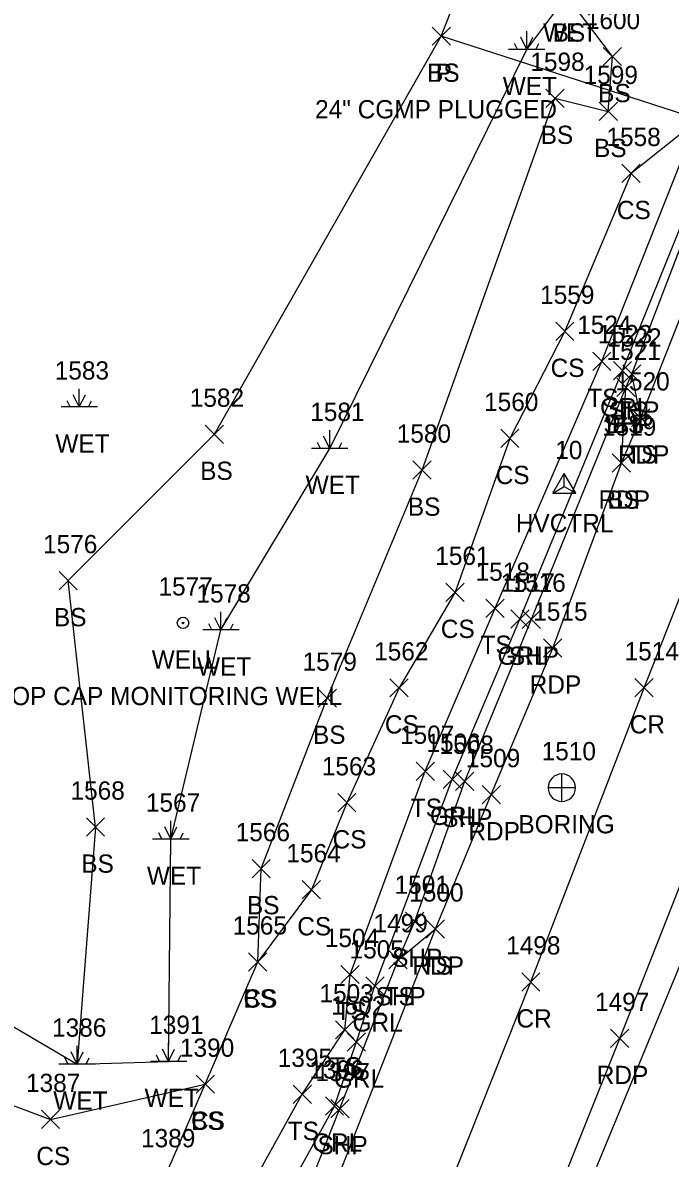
# Model space of a CAD drawing. Extents: x 1554917 to 1555870, y 813367 to 816333.
# Drawn here: x 1555138.3 to 1555209.2, y 813931.9 to 814056.2 of the extents above; entities that cross this region are included whole.
import ezdxf

# ---------------------------------------------------------------- set-up
doc = ezdxf.new("R2010")
doc.units = 0
for name, color, linetype in [('C_A', 7, 'Continuous'), ('C_I', 7, 'Continuous'), ('CPSM', 7, 'Continuous'), ('D_A', 7, 'Continuous'), ('D_C', 7, 'Continuous'), ('D_TIC', 7, 'Continuous'), ('DCP', 7, 'Continuous'), ('G_A', 7, 'Continuous'), ('G_I', 7, 'Continuous'), ('GA_P', 7, 'Continuous'), ('L_A', 7, 'Continuous'), ('L_I', 7, 'Continuous'), ('L_TIC', 7, 'Continuous'), ('LELB', 7, 'Continuous'), ('LWET', 7, 'Continuous'), ('P_A', 7, 'Continuous'), ('P_I', 7, 'Continuous'), ('P_TIC', 7, 'Continuous'), ('PET', 7, 'Continuous'), ('PRC', 7, 'Continuous'), ('PSP', 7, 'Continuous'), ('R_A', 7, 'Continuous'), ('R_I', 7, 'Continuous'), ('R_TIC', 7, 'Continuous'), ('RGR', 7, 'Continuous'), ('U_A', 7, 'Continuous'), ('U_C', 7, 'Continuous'), ('U_I', 7, 'Continuous'), ('UWW', 7, 'Continuous')]:
    doc.layers.add(name, color=color, linetype=linetype)

msp = doc.modelspace()

# ---------------------------------------------------------------- linework, layer by layer
at = {"layer": 'CPSM'}
for p, q in [((1555196.38, 814004.7), (1555197.63, 814006.87)), ((1555198.88, 814004.7), (1555197.63, 814006.87)), ((1555197.63, 814005.43), (1555197.63, 814006.87)), ((1555196.38, 814004.7), (1555197.63, 814005.43)), ((1555196.38, 814004.7), (1555198.88, 814004.7)), ((1555197.63, 814005.43), (1555197.63, 814005.43)), ((1555197.63, 814005.43), (1555198.88, 814004.7))]:
    msp.add_line(p, q, dxfattribs=at)
at = {"layer": 'D_TIC'}
for points in [[(1555183.15, 814053.74), (1555185.15, 814055.74)], [(1555185.15, 814053.74), (1555183.15, 814055.74)]]:
    msp.add_lwpolyline(points, dxfattribs=at)
at = {"layer": 'DCP'}
msp.add_lwpolyline([(1555254.85, 814031.94), (1555184.15, 814054.74)], dxfattribs=at)
at = {"layer": 'GA_P'}
for p, q in [((1555197.37, 813972.46), (1555197.37, 813973.96)), ((1555197.37, 813972.46), (1555195.87, 813972.46)), ((1555198.87, 813972.46), (1555197.37, 813972.46)), ((1555197.37, 813970.96), (1555197.37, 813972.46))]:
    msp.add_line(p, q, dxfattribs=at)
for start, end in [(90, 180), (0, 90), (180, 270), (270, 0)]:
    msp.add_arc((1555197.37, 813972.46), 1.5, start, end, dxfattribs=at)
at = {"layer": 'L_TIC'}
for points in [[(1555183.15, 814053.74), (1555185.15, 814055.74)], [(1555185.15, 814053.74), (1555183.15, 814055.74)], [(1555201.9, 814051.51), (1555203.9, 814053.51)], [(1555203.9, 814051.51), (1555201.9, 814053.51)], [(1555195.6, 814046.94), (1555197.6, 814048.94)], [(1555197.6, 814046.94), (1555195.6, 814048.94)], [(1555201.45, 814045.5), (1555203.45, 814047.5)], [(1555203.45, 814045.5), (1555201.45, 814047.5)], [(1555203.95, 814038.71), (1555205.95, 814040.71)], [(1555205.95, 814038.71), (1555203.95, 814040.71)], [(1555196.69, 814021.43), (1555198.69, 814023.43)], [(1555198.69, 814021.43), (1555196.69, 814023.43)], [(1555200.74, 814018.14), (1555202.74, 814020.14)], [(1555202.74, 814018.14), (1555200.74, 814020.14)], [(1555204.03, 814016.75), (1555206.03, 814018.75)], [(1555206.03, 814016.75), (1555204.03, 814018.75)], [(1555203.38, 814015.29), (1555205.38, 814017.29)], [(1555205.38, 814015.29), (1555203.38, 814017.29)], [(1555205.01, 814011.95), (1555207.01, 814013.95)], [(1555207.01, 814011.95), (1555205.01, 814013.95)], [(1555158.28, 814010.16), (1555160.28, 814012.16)], [(1555160.28, 814010.16), (1555158.28, 814012.16)], [(1555190.66, 814009.7), (1555192.66, 814011.7)], [(1555192.66, 814009.7), (1555190.66, 814011.7)], [(1555181.05, 814006.23), (1555183.05, 814008.23)], [(1555183.05, 814006.23), (1555181.05, 814008.23)], [(1555202.89, 814007), (1555204.89, 814009)], [(1555204.89, 814007), (1555202.89, 814009)], [(1555142.26, 813994.13), (1555144.26, 813996.13)], [(1555144.26, 813994.13), (1555142.26, 813996.13)], [(1555184.66, 813992.85), (1555186.66, 813994.85)], [(1555186.66, 813992.85), (1555184.66, 813994.85)], [(1555189.04, 813991.11), (1555191.04, 813993.11)], [(1555191.04, 813991.11), (1555189.04, 813993.11)], [(1555178.53, 813982.39), (1555180.53, 813984.39)], [(1555180.53, 813982.39), (1555178.53, 813984.39)], [(1555170.65, 813981.26), (1555172.65, 813983.26)], [(1555172.65, 813981.26), (1555170.65, 813983.26)], [(1555181.4, 813973.26), (1555183.4, 813975.26)], [(1555183.4, 813973.26), (1555181.4, 813975.26)], [(1555172.8, 813969.81), (1555174.8, 813971.81)], [(1555174.8, 813969.81), (1555172.8, 813971.81)], [(1555145.26, 813967.15), (1555147.26, 813969.15)], [(1555147.26, 813967.15), (1555145.26, 813969.15)], [(1555163.41, 813962.6), (1555165.41, 813964.6)], [(1555165.41, 813962.6), (1555163.41, 813964.6)], [(1555168.92, 813960.29), (1555170.92, 813962.29)], [(1555170.92, 813960.29), (1555168.92, 813962.29)], [(1555182.5, 813955.99), (1555184.5, 813957.99)], [(1555184.5, 813955.99), (1555182.5, 813957.99)], [(1555163.03, 813952.38), (1555165.03, 813954.38)], [(1555165.03, 813952.38), (1555163.03, 813954.38)], [(1555163.03, 813952.38), (1555165.03, 813954.38)], [(1555165.03, 813952.38), (1555163.03, 813954.38)], [(1555178.42, 813952.63), (1555180.42, 813954.63)], [(1555180.42, 813952.63), (1555178.42, 813954.63)], [(1555173.16, 813951.01), (1555175.16, 813953.01)], [(1555175.16, 813951.01), (1555173.16, 813953.01)], [(1555172.57, 813944.95), (1555174.57, 813946.95)], [(1555174.57, 813944.95), (1555172.57, 813946.95)], [(1555157.29, 813939), (1555159.29, 813941)], [(1555159.29, 813939), (1555157.29, 813941)], [(1555157.29, 813939), (1555159.29, 813941)], [(1555159.29, 813939), (1555157.29, 813941)], [(1555167.92, 813937.89), (1555169.92, 813939.89)], [(1555169.92, 813937.89), (1555167.92, 813939.89)], [(1555140.33, 813935.14), (1555142.33, 813937.14)], [(1555142.33, 813935.14), (1555140.33, 813937.14)]]:
    msp.add_lwpolyline(points, dxfattribs=at)
at = {"layer": 'LELB'}
for points in [[(1555161.57, 813925.65), (1555168.92, 813938.89), (1555173.57, 813945.95), (1555174.16, 813952.01), (1555182.4, 813974.26), (1555190.04, 813992.11), (1555201.74, 814019.14), (1555212.19, 814045.46), (1555215.96, 814054.45), (1555221.93, 814072.78), (1555233.01, 814105.58), (1555244.12, 814126.91), (1555239.17, 814141.42), (1555241.48, 814149.75), (1555239.8, 814159.84), (1555236.73, 814168.01), (1555231.65, 814185.57), (1555238.6, 814201.71), (1555239.91, 814224.12), (1555242.5, 814231.73), (1555248.59, 814255.34), (1555259.33, 814293.88), (1555265.42, 814329.58), (1555267.14, 814335.72)], [(1555153.95, 813930.09), (1555158.29, 813940), (1555164.03, 813953.38), (1555164.41, 813963.6), (1555171.65, 813982.26), (1555182.05, 814007.23), (1555196.6, 814047.94), (1555202.45, 814046.5), (1555202.9, 814052.51), (1555197.92, 814059.14), (1555209.24, 814082.57), (1555225.19, 814108.48), (1555231.76, 814126.55), (1555232.99, 814141.48), (1555234.22, 814150.46), (1555236.77, 814156.09), (1555225.98, 814163.26)], [(1555146.26, 813968.15), (1555143.26, 813995.13), (1555159.28, 814011.16), (1555184.15, 814054.74), (1555197, 814087.34), (1555204.67, 814115.04), (1555215.8, 814144.46), (1555222.11, 814148.5), (1555231.58, 814148.96), (1555234.22, 814150.46)], [(1555212.19, 814045.46), (1555204.95, 814039.71), (1555197.69, 814022.43), (1555191.66, 814010.7), (1555185.66, 813993.85), (1555179.53, 813983.39), (1555173.8, 813970.81), (1555169.92, 813961.29), (1555164.03, 813953.38)], [(1555206.01, 814012.95), (1555205.03, 814017.75)], [(1555203.89, 814008), (1555204.38, 814016.29)], [(1555146.26, 813968.15), (1555144.25, 813942.2)], [(1555111.92, 813965.76), (1555119.76, 813951.5), (1555131.06, 813939.98), (1555141.33, 813936.14), (1555158.29, 813940)], [(1555179.42, 813953.63), (1555183.5, 813956.99)]]:
    msp.add_lwpolyline(points, dxfattribs=at)
at = {"layer": 'LWET'}
for p, q in [((1555193.51, 814053.28), (1555192.85, 814054.62)), ((1555193.51, 814053.28), (1555193.51, 814055.28)), ((1555193.51, 814053.28), (1555194.18, 814054.62)), ((1555195.51, 814053.28), (1555191.51, 814053.28)), ((1555192.51, 814053.28), (1555192.18, 814053.95)), ((1555194.51, 814053.28), (1555194.85, 814053.95)), ((1555144.48, 814014.14), (1555144.48, 814016.14)), ((1555143.48, 814014.14), (1555143.15, 814014.81)), ((1555144.48, 814014.14), (1555143.81, 814015.48)), ((1555144.48, 814014.14), (1555145.15, 814015.48)), ((1555145.48, 814014.14), (1555145.81, 814014.81)), ((1555146.48, 814014.14), (1555142.48, 814014.14)), ((1555171.92, 814009.61), (1555171.25, 814010.94)), ((1555171.92, 814009.61), (1555171.92, 814011.61)), ((1555171.92, 814009.61), (1555172.58, 814010.94)), ((1555173.92, 814009.61), (1555169.92, 814009.61)), ((1555170.92, 814009.61), (1555170.58, 814010.27)), ((1555172.92, 814009.61), (1555173.25, 814010.27)), ((1555160.01, 813989.73), (1555159.34, 813991.07)), ((1555160.01, 813989.73), (1555160.01, 813991.73)), ((1555160.01, 813989.73), (1555160.68, 813991.07)), ((1555162.01, 813989.73), (1555158.01, 813989.73)), ((1555159.01, 813989.73), (1555158.68, 813990.4)), ((1555161.01, 813989.73), (1555161.34, 813990.4)), ((1555154.52, 813966.83), (1555154.52, 813968.83)), ((1555153.52, 813966.83), (1555153.18, 813967.5)), ((1555154.52, 813966.83), (1555153.85, 813968.17)), ((1555154.52, 813966.83), (1555155.18, 813968.17)), ((1555155.52, 813966.83), (1555155.85, 813967.5)), ((1555156.52, 813966.83), (1555152.52, 813966.83)), ((1555144.25, 813942.2), (1555144.25, 813944.2)), ((1555154.27, 813942.5), (1555153.6, 813943.83)), ((1555154.27, 813942.5), (1555154.27, 813944.5)), ((1555154.27, 813942.5), (1555154.93, 813943.83)), ((1555143.25, 813942.2), (1555142.91, 813942.87)), ((1555144.25, 813942.2), (1555143.58, 813943.53)), ((1555144.25, 813942.2), (1555144.91, 813943.53)), ((1555145.25, 813942.2), (1555145.58, 813942.87)), ((1555156.27, 813942.5), (1555152.27, 813942.5)), ((1555153.27, 813942.5), (1555152.93, 813943.16)), ((1555155.27, 813942.5), (1555155.6, 813943.16)), ((1555146.25, 813942.2), (1555142.25, 813942.2))]:
    msp.add_line(p, q, dxfattribs=at)
msp.add_lwpolyline([(1555079.52, 813972.15), (1555098.48, 813965.44), (1555111.92, 813965.76), (1555124.09, 813958.62), (1555134.73, 813947.78), (1555144.25, 813942.2), (1555154.27, 813942.5), (1555154.52, 813966.83), (1555160.01, 813989.73), (1555171.92, 814009.61), (1555193.51, 814053.28), (1555197.92, 814059.14), (1555201.96, 814084.83), (1555215.92, 814112.52), (1555222.38, 814128.7), (1555225.01, 814142.8)], dxfattribs=at)
at = {"layer": 'P_TIC'}
for points in [[(1555204.03, 814016.75), (1555206.03, 814018.75)], [(1555206.03, 814016.75), (1555204.03, 814018.75)], [(1555203.38, 814015.29), (1555205.38, 814017.29)], [(1555205.38, 814015.29), (1555203.38, 814017.29)], [(1555205.01, 814011.95), (1555207.01, 814013.95)], [(1555207.01, 814011.95), (1555205.01, 814013.95)], [(1555202.89, 814007), (1555204.89, 814009)], [(1555204.89, 814007), (1555202.89, 814009)], [(1555193.02, 813989.9), (1555195.02, 813991.9)], [(1555195.02, 813989.9), (1555193.02, 813991.9)], [(1555195.36, 813986.75), (1555197.36, 813988.75)], [(1555197.36, 813986.75), (1555195.36, 813988.75)], [(1555205.37, 813982.4), (1555207.37, 813984.4)], [(1555207.37, 813982.4), (1555205.37, 813984.4)], [(1555185.72, 813972.16), (1555187.72, 813974.16)], [(1555187.72, 813972.16), (1555185.72, 813974.16)], [(1555188.63, 813970.7), (1555190.63, 813972.7)], [(1555190.63, 813970.7), (1555188.63, 813972.7)], [(1555180.24, 813956.84), (1555182.24, 813958.84)], [(1555182.24, 813956.84), (1555180.24, 813958.84)], [(1555182.5, 813955.99), (1555184.5, 813957.99)], [(1555184.5, 813955.99), (1555182.5, 813957.99)], [(1555178.42, 813952.63), (1555180.42, 813954.63)], [(1555180.42, 813952.63), (1555178.42, 813954.63)], [(1555192.96, 813950.2), (1555194.96, 813952.2)], [(1555194.96, 813950.2), (1555192.96, 813952.2)], [(1555202.7, 813944.01), (1555204.7, 813946.01)], [(1555204.7, 813944.01), (1555202.7, 813946.01)], [(1555172.05, 813936.33), (1555174.05, 813938.33)], [(1555174.05, 813936.33), (1555172.05, 813938.33)]]:
    msp.add_lwpolyline(points, dxfattribs=at)
at = {"layer": 'PET'}
for points in [[(1555161.36, 813900.53), (1555183.5, 813956.99), (1555189.63, 813971.7), (1555196.36, 813987.75), (1555203.89, 814008), (1555206.01, 814012.95), (1555218.07, 814043.52), (1555227.32, 814068.19), (1555240.79, 814103.21), (1555254.41, 814137.22), (1555273.72, 814186.43), (1555286.72, 814219.57), (1555303.34, 814262.32), (1555319.11, 814302.56), (1555330.34, 814331.97)], [(1555182.57, 813892.25), (1555203.7, 813945.01), (1555216.85, 813978.34), (1555228.72, 814008.85), (1555239.47, 814035.47), (1555248.64, 814059.88), (1555262.92, 814096.01), (1555276.68, 814131.3), (1555286.36, 814156.33), (1555297.11, 814184.04), (1555306.67, 814209.51), (1555324.28, 814253.26), (1555340.35, 814293.54), (1555352.6, 814325.05)]]:
    msp.add_lwpolyline(points, dxfattribs=at)
at = {"layer": 'PRC'}
msp.add_lwpolyline([(1554976.76, 813382.18), (1554992.84, 813427.9), (1555014.07, 813486.01), (1555030.62, 813532.31), (1555046.37, 813573.08), (1555064.69, 813621.19), (1555082.41, 813667.53), (1555112.1, 813744.1), (1555110.69, 813739.79), (1555136.16, 813805.74), (1555152.52, 813846.93), (1555172.03, 813896.18), (1555193.96, 813951.2), (1555206.37, 813983.4), (1555218.13, 814013.22), (1555228.65, 814039.26), (1555237.93, 814064.31), (1555252.22, 814099.76), (1555265.8, 814135.89), (1555275.26, 814160.09), (1555297.17, 814214.77), (1555313.83, 814257.94), (1555329.72, 814298.26), (1555342.03, 814329.92)], dxfattribs=at)
at = {"layer": 'PSP'}
for points in [[(1555160.79, 813906.47), (1555173.05, 813937.33), (1555179.42, 813953.63), (1555181.24, 813957.84), (1555186.72, 813973.16), (1555194.02, 813990.9), (1555204.38, 814016.29), (1555205.03, 814017.75), (1555215.29, 814044.5), (1555224.66, 814068.93), (1555238.68, 814103.48), (1555248.96, 814130.73), (1555261.62, 814162.67), (1555270.99, 814187.05), (1555283.98, 814220.8), (1555300.65, 814263.34), (1555316.51, 814303.51), (1555327.36, 814331.38)], [(1555197.67, 813922.42), (1555211.91, 813956.86), (1555220.23, 813977.15), (1555231.8, 814008.2), (1555242.48, 814034.48), (1555251.86, 814058.97), (1555266.04, 814094.8), (1555272.79, 814112.73), (1555286.23, 814147.2), (1555300.19, 814183.09), (1555310.34, 814208.22), (1555327.38, 814252.3), (1555343.49, 814292.44), (1555355.29, 814323.57)]]:
    msp.add_lwpolyline(points, dxfattribs=at)
at = {"layer": 'R_TIC'}
for points in [[(1555203.01, 814017.12), (1555205.01, 814019.12)], [(1555205.01, 814017.12), (1555203.01, 814019.12)], [(1555191.77, 813989.92), (1555193.77, 813991.92)], [(1555193.77, 813989.92), (1555191.77, 813991.92)], [(1555184.36, 813972.38), (1555186.36, 813974.38)], [(1555186.36, 813972.38), (1555184.36, 813974.38)], [(1555175.88, 813949.76), (1555177.88, 813951.76)], [(1555177.88, 813949.76), (1555175.88, 813951.76)], [(1555173.85, 813943.62), (1555175.85, 813945.62)], [(1555175.85, 813943.62), (1555173.85, 813945.62)], [(1555171.45, 813936.61), (1555173.45, 813938.61)], [(1555173.45, 813936.61), (1555171.45, 813938.61)]]:
    msp.add_lwpolyline(points, dxfattribs=at)
at = {"layer": 'RGR'}
msp.add_lwpolyline([(1555159.27, 813917.51), (1555164.57, 813923.33), (1555172.45, 813937.61), (1555174.85, 813944.62), (1555176.88, 813950.76), (1555185.36, 813973.38), (1555192.77, 813990.92), (1555204.01, 814018.12), (1555214.74, 814044.68), (1555224.38, 814069.2), (1555237.86, 814103.71), (1555245.14, 814124.79), (1555246.27, 814138.04)], dxfattribs=at)
at = {"layer": 'UWW'}
for radius in [0.625, 0.0833]:
    msp.add_circle((1555155.85, 813990.5), radius, dxfattribs=at)

# ---------------------------------------------------------------- texts
at = {"layer": 'C_A'}
msp.add_text('HVCTRL', height=2, dxfattribs=at).set_placement((1555192.32, 814000.43))
at = {"layer": 'C_I'}
msp.add_text('10', height=2, dxfattribs=at).set_placement((1555196.64, 814008.43))
at = {"layer": 'D_A'}
msp.add_text('P', height=2, dxfattribs=at).set_placement((1555183.53, 814049.74))
at = {"layer": 'D_C'}
msp.add_text('24" CGMP PLUGGED', height=2, dxfattribs=at).set_placement((1555170.32, 814045.74))
at = {"layer": 'G_A'}
msp.add_text('BORING', height=2, dxfattribs=at).set_placement((1555192.6, 813967.46))
at = {"layer": 'G_I'}
msp.add_text('1510', height=2, dxfattribs=at).set_placement((1555195.15, 813975.46))
at = {"layer": 'L_A'}
for s, p in [('WET', (1555195.3, 814054.14)), ('BS', (1555196.36, 814054.14)), ('BS', (1555182.59, 814049.74)), ('WET', (1555190.89, 814048.28)), ('BS', (1555201.34, 814047.51)), ('BS', (1555195.04, 814042.94)), ('BS', (1555200.89, 814041.5)), ('CS', (1555203.39, 814034.71)), ('CS', (1555196.13, 814017.43)), ('TS', (1555200.15, 814014.14)), ('TS', (1555203.44, 814012.75)), ('BS', (1555202.82, 814011.29)), ('WET', (1555141.86, 814009.14)), ('TS', (1555204.42, 814007.95)), ('BS', (1555157.73, 814006.16)), ('CS', (1555190.11, 814005.7)), ('WET', (1555169.29, 814004.61)), ('BS', (1555202.33, 814003)), ('BS', (1555180.49, 814002.23)), ('BS', (1555141.7, 813990.13)), ('CS', (1555184.1, 813988.85)), ('TS', (1555188.45, 813987.11)), ('WET', (1555157.39, 813984.73)), ('CS', (1555177.97, 813978.39)), ('BS', (1555170.09, 813977.26)), ('TS', (1555180.81, 813969.26)), ('CS', (1555172.24, 813965.81)), ('BS', (1555144.7, 813963.15)), ('WET', (1555151.89, 813961.83)), ('BS', (1555162.85, 813958.6)), ('CS', (1555168.37, 813956.29)), ('TS', (1555181.91, 813951.99)), ('CS', (1555162.47, 813948.38)), ('BS', (1555162.47, 813948.38)), ('TS', (1555177.83, 813948.63)), ('TS', (1555172.57, 813947.01)), ('TS', (1555171.98, 813940.95)), ('WET', (1555141.63, 813937.2)), ('WET', (1555151.64, 813937.5)), ('CS', (1555156.73, 813935)), ('BS', (1555156.73, 813935)), ('TS', (1555167.33, 813933.89)), ('CS', (1555139.77, 813931.14))]:
    msp.add_text(s, height=2, dxfattribs=at).set_placement(p)
at = {"layer": 'L_I'}
for s, p in [('1600', (1555199.99, 814055.51)), ('1598', (1555193.91, 814050.94)), ('1599', (1555199.75, 814049.5)), ('1558', (1555202.25, 814042.71)), ('1559', (1555194.98, 814025.43)), ('1524', (1555199.05, 814022.14)), ('1522', (1555202.34, 814020.75)), ('1521', (1555202.26, 814019.29)), ('1583', (1555141.79, 814017.14)), ('1520', (1555203.23, 814015.95)), ('1582', (1555156.59, 814014.16)), ('1560', (1555188.84, 814013.7)), ('1581', (1555169.79, 814012.61)), ('1580', (1555179.27, 814010.23)), ('1519', (1555201.76, 814011)), ('1576', (1555140.51, 813998.13)), ('1561', (1555183.49, 813996.85)), ('1518', (1555187.91, 813995.11)), ('1578', (1555157.32, 813992.73)), ('1562', (1555176.79, 813986.39)), ('1579', (1555168.95, 813985.26)), ('1507', (1555179.63, 813977.26)), ('1563', (1555171.06, 813973.81)), ('1568', (1555143.52, 813971.15)), ('1567', (1555151.78, 813969.83)), ('1566', (1555161.62, 813966.6)), ('1564', (1555167.18, 813964.29)), ('1500', (1555180.64, 813959.99)), ('1499', (1555176.72, 813956.63)), ('1565', (1555161.29, 813956.38)), ('1565', (1555161.29, 813956.38)), ('1504', (1555171.39, 813955.01)), ('1503', (1555170.8, 813948.95)), ('1391', (1555152.14, 813945.5)), ('1386', (1555141.5, 813945.2)), ('1390', (1555155.51, 813943)), ('1390', (1555155.51, 813943)), ('1395', (1555166.23, 813941.89)), ('1387', (1555138.64, 813939.14)), ('1389', (1555151.25, 813933.09)), ('1389', (1555151.25, 813933.09))]:
    msp.add_text(s, height=2, dxfattribs=at).set_placement(p)
at = {"layer": 'P_A'}
for s, p in [('SHP', (1555202.56, 814012.75)), ('SHP', (1555201.92, 814011.29)), ('RDP', (1555203.5, 814007.95)), ('RDP', (1555201.38, 814003)), ('SHP', (1555191.56, 813985.9)), ('RDP', (1555193.84, 813982.75)), ('CR', (1555204.8, 813978.4)), ('SHP', (1555184.26, 813968.16)), ('RDP', (1555187.12, 813966.7)), ('SHP', (1555178.77, 813952.84)), ('RDP', (1555180.99, 813951.99)), ('SHP', (1555176.95, 813948.63)), ('CR', (1555192.39, 813946.2)), ('RDP', (1555201.19, 813940.01)), ('SHP', (1555170.59, 813932.33))]:
    msp.add_text(s, height=2, dxfattribs=at).set_placement(p)
at = {"layer": 'P_I'}
for s, p in [('1522', (1555202.34, 814020.75)), ('1521', (1555202.26, 814019.29)), ('1520', (1555203.23, 814015.95)), ('1519', (1555201.76, 814011)), ('1516', (1555191.84, 813993.9)), ('1515', (1555194.23, 813990.75)), ('1514', (1555204.24, 813986.4)), ('1508', (1555183.95, 813976.16)), ('1509', (1555186.85, 813974.7)), ('1501', (1555179.03, 813960.84)), ('1500', (1555180.64, 813959.99)), ('1499', (1555176.72, 813956.63)), ('1498', (1555191.26, 813954.2)), ('1497', (1555201, 813948.01)), ('1397', (1555170.36, 813940.33))]:
    msp.add_text(s, height=2, dxfattribs=at).set_placement(p)
at = {"layer": 'R_A'}
for p in [(1555201.55, 814013.12), (1555190.31, 813985.92), (1555182.9, 813968.38), (1555174.42, 813945.76), (1555172.39, 813939.62), (1555169.99, 813932.61)]:
    msp.add_text('GRL', height=2, dxfattribs=at).set_placement(p)
at = {"layer": 'R_I'}
for s, p in [('1523', (1555201.31, 814021.12)), ('1517', (1555190.64, 813993.92)), ('1506', (1555182.53, 813976.38)), ('1505', (1555174.1, 813953.76)), ('1502', (1555172.07, 813947.62)), ('1396', (1555169.7, 813940.61))]:
    msp.add_text(s, height=2, dxfattribs=at).set_placement(p)
at = {"layer": 'U_A'}
msp.add_text('WELL', height=2, dxfattribs=at).set_placement((1555152.42, 813985.5))
at = {"layer": 'U_C'}
msp.add_text('TOP CAP MONITORING WELL', height=2, dxfattribs=at).set_placement((1555135.38, 813981.5))
at = {"layer": 'U_I'}
msp.add_text('1577', height=2, dxfattribs=at).set_placement((1555153.16, 813993.5))

doc.saveas('drawing.dxf')
